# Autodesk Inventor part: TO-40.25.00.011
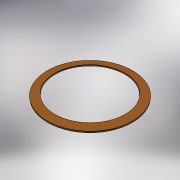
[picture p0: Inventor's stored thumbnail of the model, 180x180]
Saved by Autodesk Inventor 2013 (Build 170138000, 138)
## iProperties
Created: 2012-02
Part Number: TO-40.25.00.011
Material: Bronze, Soft Tin
Document SubType Name: Modeling
Designer: tedescj
Mass: 30.5184 g
Surface Area: 54.1734 cm^2
Volume: 3.43908 cm^3
Density: 8.874 g/cm^3
Author: tedescj
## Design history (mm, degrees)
sketch "Sketch1"
  geometry: C1 r 48.268 at (0, 0) reference; 1 further point
  constraints: 1 centre point, 2 other
extrude "Extrusion1" new body sketch "Sketch1" distance "d0" = 1.5; taper "d1" = 0 deg
sketch "Sketch2"
  geometry: C1 r 40 at (0, 0) reference; 1 further point
  constraints: 1 centre point, 2 other
extrude "Extrusion2" cut sketch "Sketch2" stored distance "d2" = 1.5; taper "d3" = 0 deg
body "Solid1"
